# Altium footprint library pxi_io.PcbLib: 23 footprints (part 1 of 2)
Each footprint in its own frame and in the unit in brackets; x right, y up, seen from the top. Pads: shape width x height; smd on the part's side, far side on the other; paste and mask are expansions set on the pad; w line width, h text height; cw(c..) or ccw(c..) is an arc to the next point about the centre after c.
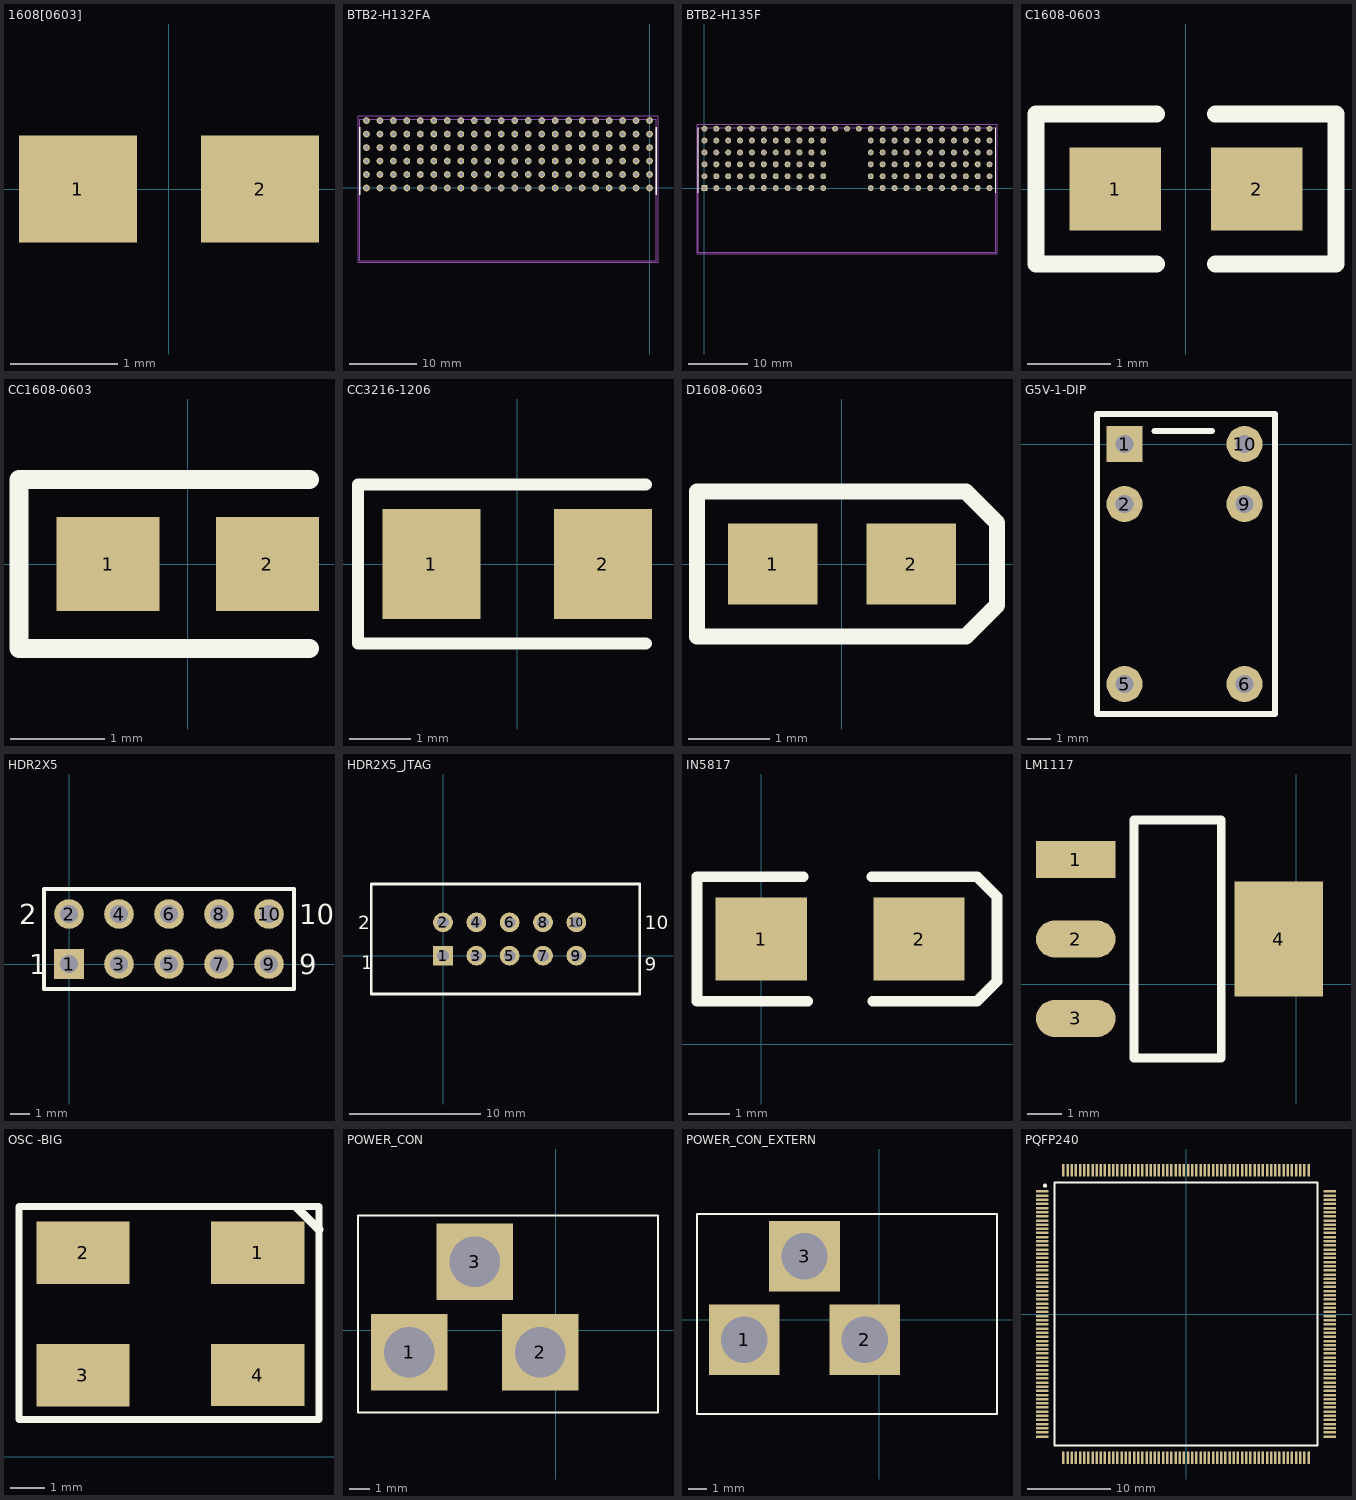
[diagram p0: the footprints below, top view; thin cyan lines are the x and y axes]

## 1608[0603] [mm] "Chip Capacitor; Body 1.6 x 0.8 mm (LxW typ)"
height 1.35
pads (2):
  rect 1.1x1 smd: 1(-0.85,0) 2(0.85,0)

## BTB2-H132FA [mm] "Board-to-Board Connector, Right Angle, Pitch 2mm, 132-Position, Female"
height 7.7
pads (132):
  round 1 hole 0.61: A1(0,0) A2(-2,0) A3(-4,0) A4(-6,0) A5(-8,0) A6(-10,0) A7(-12,0) A8(-14,0) A9(-16,0) A10(-18,0) A11(-20,0) A12(-22,0) A13(-24,0) A14(-26,0) A15(-28,0) A16(-30,0) A17(-32,0) A18(-34,0) A19(-36,0) A20(-38,0) A21(-40,0) A22(-42,0) B1(0,2) B2(-2,2) B3(-4,2) B4(-6,2) B5(-8,2) B6(-10,2) B7(-12,2) B8(-14,2) B9(-16,2) B10(-18,2) B11(-20,2) B12(-22,2) B13(-24,2) B14(-26,2) B15(-28,2) B16(-30,2) B17(-32,2) B18(-34,2) B19(-36,2) B20(-38,2) B21(-40,2) B22(-42,2) C1(0,4) C2(-2,4) C3(-4,4) C4(-6,4) C5(-8,4) C6(-10,4) C7(-12,4) C8(-14,4) C9(-16,4) C10(-18,4) C11(-20,4) C12(-22,4) C13(-24,4) C14(-26,4) C15(-28,4) C16(-30,4) C17(-32,4) C18(-34,4) C19(-36,4) C20(-38,4) C21(-40,4) C22(-42,4) D1(0,6) D2(-2,6) D3(-4,6) D4(-6,6) D5(-8,6) D6(-10,6) D7(-12,6) D8(-14,6) D9(-16,6) D10(-18,6) D11(-20,6) D12(-22,6) D13(-24,6) D14(-26,6) D15(-28,6) D16(-30,6) D17(-32,6) D18(-34,6) D19(-36,6) D20(-38,6) D21(-40,6) D22(-42,6) E1(0,8) E2(-2,8) E3(-4,8) E4(-6,8) E5(-8,8) E6(-10,8) E7(-12,8) E8(-14,8) E9(-16,8) E10(-18,8) E11(-20,8) E12(-22,8) E13(-24,8) E14(-26,8) E15(-28,8) E16(-30,8) E17(-32,8) E18(-34,8) E19(-36,8) E20(-38,8) E21(-40,8) E22(-42,8) F1(0,10) F2(-2,10) F3(-4,10) F4(-6,10) F5(-8,10) F6(-10,10) F7(-12,10) F8(-14,10) F9(-16,10) F10(-18,10) F11(-20,10) F12(-22,10) F13(-24,10) F14(-26,10) F15(-28,10) F16(-30,10) F17(-32,10) F18(-34,10) F19(-36,10) F20(-38,10) F21(-40,10) F22(-42,10)
Top Overlay:
  lines w0.2: -43,-1 -43,9 ; 1,-1 1,9
Mechanical 13:
  lines w0.1: -43,-10.8 -43,10.2 1,10.2 1,-10.8 -43,-10.8
Mechanical 15:
  lines w0.1: -0.5,0 0.5,0 ; 0,-0.5 0,0.5 ; -43.25,-11.05 1.25,-11.05 1.25,10.75 -43.25,10.75 -43.25,-11.05
3D body: height 7.25, standoff 0, extent -43,-2 1,9.4
3D body: height 7.7, standoff -3.7, extent -43,-10.8 0.95,-2.032
3D body: height 7.39, standoff 0.7, extent -42.418,9.8 0.65,10.2
3D body: height 7.8, standoff 7.39, extent -42.418,0.972 0.65,10.2
3D body: height 7.8, standoff 7.39, extent -42.418,-6.38 0.65,0.972
3D body: height 0, standoff -3.3, extent -0.198,-0.199 0.2,0.2
3D body: height 0, standoff -3.3, extent -0.198,1.801 0.2,2.2
3D body: height 0, standoff -3.3, extent -0.198,3.801 0.2,4.2
3D body: height 0, standoff -3.3, extent -0.198,5.801 0.2,6.2
3D body: height 0, standoff -3.3, extent -0.198,7.801 0.2,8.2
3D body: height 0, standoff -3.3, extent -2.198,7.801 -1.8,8.2
3D body: height 0, standoff -3.3, extent -2.198,5.801 -1.8,6.2
3D body: height 0, standoff -3.3, extent -2.198,3.801 -1.8,4.2
3D body: height 0, standoff -3.3, extent -2.198,1.801 -1.8,2.2
3D body: height 0, standoff -3.3, extent -2.198,-0.199 -1.8,0.2
3D body: height 0, standoff -3.3, extent -4.198,7.801 -3.8,8.2
3D body: height 0, standoff -3.3, extent -4.198,5.801 -3.8,6.2
3D body: height 0, standoff -3.3, extent -4.198,3.801 -3.8,4.2
3D body: height 0, standoff -3.3, extent -4.198,1.801 -3.8,2.2
3D body: height 0, standoff -3.3, extent -4.198,-0.199 -3.8,0.2
3D body: height 0, standoff -3.3, extent -6.198,7.801 -5.8,8.2
3D body: height 0, standoff -3.3, extent -6.198,5.801 -5.8,6.2
3D body: height 0, standoff -3.3, extent -6.198,3.801 -5.8,4.2
3D body: height 0, standoff -3.3, extent -6.198,1.801 -5.8,2.2
3D body: height 0, standoff -3.3, extent -6.198,-0.199 -5.8,0.2
3D body: height 0, standoff -3.3, extent -8.198,7.801 -7.8,8.2
3D body: height 0, standoff -3.3, extent -8.198,5.801 -7.8,6.2
3D body: height 0, standoff -3.3, extent -8.198,3.801 -7.8,4.2
3D body: height 0, standoff -3.3, extent -8.198,1.801 -7.8,2.2
3D body: height 0, standoff -3.3, extent -8.198,-0.199 -7.8,0.2
3D body: height 0, standoff -3.3, extent -10.198,7.801 -9.8,8.2
3D body: height 0, standoff -3.3, extent -10.198,5.801 -9.8,6.2
3D body: height 0, standoff -3.3, extent -10.198,3.801 -9.8,4.2
3D body: height 0, standoff -3.3, extent -10.198,1.801 -9.8,2.2
3D body: height 0, standoff -3.3, extent -10.198,-0.199 -9.8,0.2
3D body: height 0, standoff -3.3, extent -12.198,7.801 -11.8,8.2
3D body: height 0, standoff -3.3, extent -12.198,5.801 -11.8,6.2
3D body: height 0, standoff -3.3, extent -12.198,3.801 -11.8,4.2
3D body: height 0, standoff -3.3, extent -12.198,1.801 -11.8,2.2
3D body: height 0, standoff -3.3, extent -12.198,-0.199 -11.8,0.2
3D body: height 0, standoff -3.3, extent -14.198,7.801 -13.8,8.2
3D body: height 0, standoff -3.3, extent -14.198,5.801 -13.8,6.2
3D body: height 0, standoff -3.3, extent -14.198,3.801 -13.8,4.2
3D body: height 0, standoff -3.3, extent -14.198,1.801 -13.8,2.2
3D body: height 0, standoff -3.3, extent -14.198,-0.199 -13.8,0.2
3D body: height 0, standoff -3.3, extent -16.198,7.801 -15.8,8.2
3D body: height 0, standoff -3.3, extent -16.198,5.801 -15.8,6.2
3D body: height 0, standoff -3.3, extent -16.198,3.801 -15.8,4.2
3D body: height 0, standoff -3.3, extent -16.198,1.801 -15.8,2.2
3D body: height 0, standoff -3.3, extent -16.198,-0.199 -15.8,0.2
3D body: height 0, standoff -3.3, extent -18.198,7.801 -17.8,8.2
3D body: height 0, standoff -3.3, extent -18.198,5.801 -17.8,6.2
3D body: height 0, standoff -3.3, extent -18.198,3.801 -17.8,4.2
3D body: height 0, standoff -3.3, extent -18.198,1.801 -17.8,2.2
3D body: height 0, standoff -3.3, extent -18.198,-0.199 -17.8,0.2
3D body: height 0, standoff -3.3, extent -20.198,7.801 -19.8,8.2
3D body: height 0, standoff -3.3, extent -20.198,5.801 -19.8,6.2
3D body: height 0, standoff -3.3, extent -20.198,3.801 -19.8,4.2
3D body: height 0, standoff -3.3, extent -20.198,1.801 -19.8,2.2
3D body: height 0, standoff -3.3, extent -20.198,-0.199 -19.8,0.2
3D body: height 0, standoff -3.3, extent -22.198,7.801 -21.8,8.2
3D body: height 0, standoff -3.3, extent -22.198,5.801 -21.8,6.2
3D body: height 0, standoff -3.3, extent -22.198,3.801 -21.8,4.2
3D body: height 0, standoff -3.3, extent -22.198,1.801 -21.8,2.2
3D body: height 0, standoff -3.3, extent -22.198,-0.199 -21.8,0.2
3D body: height 0, standoff -3.3, extent -24.198,7.801 -23.8,8.2
3D body: height 0, standoff -3.3, extent -24.198,5.801 -23.8,6.2
3D body: height 0, standoff -3.3, extent -24.198,3.801 -23.8,4.2
3D body: height 0, standoff -3.3, extent -24.198,1.801 -23.8,2.2
3D body: height 0, standoff -3.3, extent -24.198,-0.199 -23.8,0.2
3D body: height 0, standoff -3.3, extent -26.198,7.801 -25.8,8.2
3D body: height 0, standoff -3.3, extent -26.198,5.801 -25.8,6.2
3D body: height 0, standoff -3.3, extent -26.198,3.801 -25.8,4.2
3D body: height 0, standoff -3.3, extent -26.198,1.801 -25.8,2.2
3D body: height 0, standoff -3.3, extent -26.198,-0.199 -25.8,0.2
3D body: height 0, standoff -3.3, extent -28.198,7.801 -27.8,8.2
3D body: height 0, standoff -3.3, extent -28.198,5.801 -27.8,6.2
3D body: height 0, standoff -3.3, extent -28.198,3.801 -27.8,4.2
3D body: height 0, standoff -3.3, extent -28.198,1.801 -27.8,2.2
3D body: height 0, standoff -3.3, extent -28.198,-0.199 -27.8,0.2
3D body: height 0, standoff -3.3, extent -30.198,7.801 -29.8,8.2
3D body: height 0, standoff -3.3, extent -30.198,5.801 -29.8,6.2
3D body: height 0, standoff -3.3, extent -30.198,3.801 -29.8,4.2
3D body: height 0, standoff -3.3, extent -30.198,1.801 -29.8,2.2
3D body: height 0, standoff -3.3, extent -30.198,-0.199 -29.8,0.2
3D body: height 0, standoff -3.3, extent -32.198,7.801 -31.8,8.2
3D body: height 0, standoff -3.3, extent -32.198,5.801 -31.8,6.2
3D body: height 0, standoff -3.3, extent -32.198,3.801 -31.8,4.2
3D body: height 0, standoff -3.3, extent -32.198,1.801 -31.8,2.2
3D body: height 0, standoff -3.3, extent -32.198,-0.199 -31.8,0.2
3D body: height 0, standoff -3.3, extent -34.198,7.801 -33.8,8.2
3D body: height 0, standoff -3.3, extent -34.198,5.801 -33.8,6.2
3D body: height 0, standoff -3.3, extent -34.198,3.801 -33.8,4.2
3D body: height 0, standoff -3.3, extent -34.198,1.801 -33.8,2.2
3D body: height 0, standoff -3.3, extent -34.198,-0.199 -33.8,0.2
3D body: height 0, standoff -3.3, extent -36.198,7.801 -35.8,8.2
3D body: height 0, standoff -3.3, extent -36.198,5.801 -35.8,6.2
3D body: height 0, standoff -3.3, extent -36.198,3.801 -35.8,4.2
3D body: height 0, standoff -3.3, extent -36.198,1.801 -35.8,2.2
3D body: height 0, standoff -3.3, extent -36.198,-0.199 -35.8,0.2
3D body: height 0, standoff -3.3, extent -38.198,-0.199 -37.8,0.2
3D body: height 0, standoff -3.3, extent -38.198,1.801 -37.8,2.2
3D body: height 0, standoff -3.3, extent -38.198,3.801 -37.8,4.2
3D body: height 0, standoff -3.3, extent -38.198,5.801 -37.8,6.2
3D body: height 0, standoff -3.3, extent -38.198,7.801 -37.8,8.2
3D body: height 0, standoff -3.3, extent -40.198,-0.199 -39.8,0.2
3D body: height 0, standoff -3.3, extent -40.198,1.801 -39.8,2.2
3D body: height 0, standoff -3.3, extent -40.198,3.801 -39.8,4.2
3D body: height 0, standoff -3.3, extent -40.198,5.801 -39.8,6.2
3D body: height 0, standoff -3.3, extent -40.198,7.801 -39.8,8.2
3D body: height 0, standoff -3.3, extent -42.198,-0.2 -41.8,0.2
3D body: height 0, standoff -3.3, extent -42.198,1.8 -41.8,2.2
3D body: height 0, standoff -3.3, extent -42.198,3.8 -41.8,4.2
3D body: height 0, standoff -3.3, extent -42.198,5.8 -41.8,6.2
3D body: height 0, standoff -3.3, extent -42.198,7.8 -41.8,8.2
3D body: height 0.7, standoff -3.3, extent -40.198,9.8 -39.8,10.2
3D body: height 0.7, standoff -3.3, extent -0.198,9.8 0.2,10.2
3D body: height 0.7, standoff -3.3, extent -4.198,9.8 -3.8,10.2
3D body: height 0.7, standoff -3.3, extent -8.198,9.8 -7.8,10.2
3D body: height 0.7, standoff -3.3, extent -12.198,9.8 -11.8,10.2
3D body: height 0.7, standoff -3.3, extent -16.198,9.8 -15.8,10.2
3D body: height 0.7, standoff -3.3, extent -20.198,9.8 -19.8,10.2
3D body: height 0.7, standoff -3.3, extent -24.198,9.8 -23.8,10.2
3D body: height 0.7, standoff -3.3, extent -28.198,9.8 -27.8,10.2
3D body: height 0.7, standoff -3.3, extent -32.198,9.8 -31.8,10.2
3D body: height 0.7, standoff -3.3, extent -36.198,9.8 -35.8,10.2

## BTB2-H135F [mm] "Board-to-Board Connector, Right Angle, Pitch 2mm, 135-Position, Female"
pads (135):
  rect 1x1 hole 0.61: A1(0,0)
  round 1 hole 0.61: A2(2,0) A3(4,0) A4(6,0) A5(8,0) A6(10,0) A7(12,0) A8(14,0) A9(16,0) A10(18,0) A11(20,0) A15(28,0) A16(30,0) A17(32,0) A18(34,0) A19(36,0) A20(38,0) A21(40,0) A22(42,0) A23(44,0) A24(46,0) A25(48,0) B1(0,2) B2(2,2) B3(4,2) B4(6,2) B5(8,2) B6(10,2) B7(12,2) B8(14,2) B9(16,2) B10(18,2) B11(20,2) B15(28,2) B16(30,2) B17(32,2) B18(34,2) B19(36,2) B20(38,2) B21(40,2) B22(42,2) B23(44,2) B24(46,2) B25(48,2) C1(0,4) C2(2,4) C3(4,4) C4(6,4) C5(8,4) C6(10,4) C7(12,4) C8(14,4) C9(16,4) C10(18,4) C11(20,4) C15(28,4) C16(30,4) C17(32,4) C18(34,4) C19(36,4) C20(38,4) C21(40,4) C22(42,4) C23(44,4) C24(46,4) C25(48,4) D1(0,6) D2(2,6) D3(4,6) D4(6,6) D5(8,6) D6(10,6) D7(12,6) D8(14,6) D9(16,6) D10(18,6) D11(20,6) D15(28,6) D16(30,6) D17(32,6) D18(34,6) D19(36,6) D20(38,6) D21(40,6) D22(42,6) D23(44,6) D24(46,6) D25(48,6) E1(0,8) E2(2,8) E3(4,8) E4(6,8) E5(8,8) E6(10,8) E7(12,8) E8(14,8) E9(16,8) E10(18,8) E11(20,8) E15(28,8) E16(30,8) E17(32,8) E18(34,8) E19(36,8) E20(38,8) E21(40,8) E22(42,8) E23(44,8) E24(46,8) E25(48,8) F1(0,10) F2(2,10) F3(4,10) F4(6,10) F5(8,10) F6(10,10) F7(12,10) F8(14,10) F9(16,10) F10(18,10) F11(20,10) F12(22,10) F13(24,10) F14(26,10) F15(28,10) F16(30,10) F17(32,10) F18(34,10) F19(36,10) F20(38,10) F21(40,10) F22(42,10) F23(44,10) F24(46,10) F25(48,10)
Top Overlay:
  lines w0.2: -1,-0.8 -1,10.2 ; 49,-0.8 49,10.2
Mechanical 13:
  lines w0.1: -1,-10.8 -1,10.2 49,10.2 49,-10.8 -1,-10.8
Mechanical 15:
  lines w0.1: -0.5,0 0.5,0 ; 0,-0.5 0,0.5 ; -1.25,-11.05 -1.25,10.75 49.25,10.75 49.25,-11.05 -1.25,-11.05
3D body: height 7.65, standoff -2.96, extent 21,-2.65 27,-2
3D body: height 7.65, standoff 7.25, extent -0.85,-2 48.85,10.2
3D body: height 7.65, standoff 0.85, extent -0.85,9.8 48.85,10.2
3D body: height 2.86, standoff -0.94, extent 27.702,7.701 28.3,8.299
3D body: height 2.86, standoff -0.94, extent 29.702,7.701 30.3,8.299
3D body: height 2.86, standoff -0.94, extent 31.702,7.701 32.3,8.299
3D body: height 2.86, standoff -0.94, extent 33.702,7.701 34.3,8.299
3D body: height 2.86, standoff -0.94, extent 35.702,7.701 36.3,8.299
3D body: height 2.86, standoff -0.94, extent 37.702,7.701 38.3,8.299
3D body: height 2.86, standoff -0.94, extent 39.702,7.701 40.3,8.299
3D body: height 2.86, standoff -0.94, extent 41.702,7.701 42.3,8.299
3D body: height 2.86, standoff -0.94, extent 43.702,7.701 44.3,8.299
3D body: height 2.86, standoff -0.94, extent 45.702,7.701 46.3,8.299
3D body: height 2.86, standoff -0.94, extent 27.702,5.701 28.3,6.299
3D body: height 2.86, standoff -0.94, extent 29.702,5.701 30.3,6.299
3D body: height 2.86, standoff -0.94, extent 31.702,5.701 32.3,6.299
3D body: height 2.86, standoff -0.94, extent 33.702,5.701 34.3,6.299
3D body: height 2.86, standoff -0.94, extent 35.702,5.701 36.3,6.299
3D body: height 2.86, standoff -0.94, extent 37.702,5.701 38.3,6.299
3D body: height 2.86, standoff -0.94, extent 39.702,5.701 40.3,6.299
3D body: height 2.86, standoff -0.94, extent 41.702,5.701 42.3,6.299
3D body: height 2.86, standoff -0.94, extent 43.702,5.701 44.3,6.299
3D body: height 2.86, standoff -0.94, extent 45.702,5.701 46.3,6.299
3D body: height 2.86, standoff -0.94, extent 47.702,5.701 48.3,6.299
3D body: height 2.86, standoff -0.94, extent 27.702,3.701 28.3,4.299
3D body: height 2.86, standoff -0.94, extent 29.702,3.701 30.3,4.299
3D body: height 2.86, standoff -0.94, extent 31.702,3.701 32.3,4.299
3D body: height 2.86, standoff -0.94, extent 33.702,3.701 34.3,4.299
3D body: height 2.86, standoff -0.94, extent 35.702,3.701 36.3,4.299
3D body: height 2.86, standoff -0.94, extent 37.702,3.701 38.3,4.299
3D body: height 2.86, standoff -0.94, extent 39.702,3.701 40.3,4.299
3D body: height 2.86, standoff -0.94, extent 41.702,3.701 42.3,4.299
3D body: height 2.86, standoff -0.94, extent 43.702,3.701 44.3,4.299
3D body: height 2.86, standoff -0.94, extent 45.702,3.701 46.3,4.299
3D body: height 2.86, standoff -0.94, extent 47.702,3.701 48.3,4.299
3D body: height 2.86, standoff -0.94, extent 27.702,1.701 28.3,2.299
3D body: height 2.86, standoff -0.94, extent 29.702,1.701 30.3,2.299
3D body: height 2.86, standoff -0.94, extent 31.702,1.701 32.3,2.299
3D body: height 2.86, standoff -0.94, extent 33.702,1.701 34.3,2.299
3D body: height 2.86, standoff -0.94, extent 35.702,1.701 36.3,2.299
3D body: height 2.86, standoff -0.94, extent 37.702,1.701 38.3,2.299
3D body: height 2.86, standoff -0.94, extent 39.702,1.701 40.3,2.299
3D body: height 2.86, standoff -0.94, extent 41.702,1.701 42.3,2.299
3D body: height 2.86, standoff -0.94, extent 43.702,1.701 44.3,2.299
3D body: height 2.86, standoff -0.94, extent 45.702,1.701 46.3,2.299
3D body: height 2.86, standoff -0.94, extent 47.702,1.701 48.3,2.299
3D body: height 2.86, standoff -0.94, extent 27.702,-0.299 28.3,0.3
3D body: height 2.86, standoff -0.94, extent 29.702,-0.299 30.3,0.3
3D body: height 2.86, standoff -0.94, extent 31.702,-0.299 32.3,0.3
3D body: height 2.86, standoff -0.94, extent 33.702,-0.299 34.3,0.3
3D body: height 2.86, standoff -0.94, extent 35.702,-0.299 36.3,0.3
3D body: height 2.86, standoff -0.94, extent 37.702,-0.299 38.3,0.3
3D body: height 2.86, standoff -0.94, extent 39.702,-0.299 40.3,0.3
3D body: height 2.86, standoff -0.94, extent 41.702,-0.299 42.3,0.3
3D body: height 2.86, standoff -0.94, extent 43.702,-0.299 44.3,0.3
3D body: height 2.86, standoff -0.94, extent 45.702,-0.299 46.3,0.3
3D body: height 2.86, standoff -0.94, extent 47.702,-0.299 48.3,0.3
3D body: height 2.86, standoff -0.94, extent -0.298,-0.299 0.3,0.299
3D body: height 2.86, standoff -0.94, extent 1.702,-0.299 2.3,0.299
3D body: height 2.86, standoff -0.94, extent 3.702,-0.299 4.3,0.299
3D body: height 2.86, standoff -0.94, extent 5.702,-0.299 6.3,0.299
3D body: height 2.86, standoff -0.94, extent 7.702,-0.299 8.3,0.299
3D body: height 2.86, standoff -0.94, extent 9.702,-0.299 10.3,0.299
3D body: height 2.86, standoff -0.94, extent 11.702,-0.299 12.3,0.299
3D body: height 2.86, standoff -0.94, extent 13.702,-0.299 14.3,0.299
3D body: height 2.86, standoff -0.94, extent 15.702,-0.299 16.3,0.299
3D body: height 2.86, standoff -0.94, extent 17.702,-0.299 18.3,0.299
3D body: height 2.86, standoff -0.94, extent 19.702,-0.299 20.3,0.299
3D body: height 2.86, standoff -0.94, extent -0.298,1.701 0.3,2.299
3D body: height 2.86, standoff -0.94, extent 1.702,1.701 2.3,2.299
3D body: height 2.86, standoff -0.94, extent 3.702,1.701 4.3,2.299
3D body: height 2.86, standoff -0.94, extent 5.702,1.701 6.3,2.299
3D body: height 2.86, standoff -0.94, extent 7.702,1.701 8.3,2.299
3D body: height 2.86, standoff -0.94, extent 9.702,1.701 10.3,2.299
3D body: height 2.86, standoff -0.94, extent 11.702,1.701 12.3,2.299
3D body: height 2.86, standoff -0.94, extent 13.702,1.701 14.3,2.299
3D body: height 2.86, standoff -0.94, extent 15.702,1.701 16.3,2.299
3D body: height 2.86, standoff -0.94, extent 17.702,1.701 18.3,2.299
3D body: height 2.86, standoff -0.94, extent 19.702,1.701 20.3,2.299
3D body: height 2.86, standoff -0.94, extent -0.298,3.701 0.3,4.299
3D body: height 2.86, standoff -0.94, extent 1.702,3.701 2.3,4.299
3D body: height 2.86, standoff -0.94, extent 3.702,3.701 4.3,4.299
3D body: height 2.86, standoff -0.94, extent 5.702,3.701 6.3,4.299
3D body: height 2.86, standoff -0.94, extent 7.702,3.701 8.3,4.299
3D body: height 2.86, standoff -0.94, extent 9.702,3.701 10.3,4.299
3D body: height 2.86, standoff -0.94, extent 11.702,3.701 12.3,4.299
3D body: height 2.86, standoff -0.94, extent 13.702,3.701 14.3,4.299
3D body: height 2.86, standoff -0.94, extent 15.702,3.701 16.3,4.299
3D body: height 2.86, standoff -0.94, extent 17.702,3.701 18.3,4.299
3D body: height 2.86, standoff -0.94, extent 19.702,3.701 20.3,4.299
3D body: height 2.86, standoff -0.94, extent 19.702,5.701 20.3,6.3
3D body: height 2.86, standoff -0.94, extent 17.702,5.701 18.3,6.3
3D body: height 2.86, standoff -0.94, extent 15.702,5.701 16.3,6.3
3D body: height 2.86, standoff -0.94, extent 13.702,5.701 14.3,6.3
3D body: height 2.86, standoff -0.94, extent 11.702,5.701 12.3,6.3
3D body: height 2.86, standoff -0.94, extent 9.702,5.701 10.3,6.3
3D body: height 2.86, standoff -0.94, extent 7.702,5.701 8.3,6.3
3D body: height 2.86, standoff -0.94, extent 5.702,5.701 6.3,6.3
3D body: height 2.86, standoff -0.94, extent 3.702,5.701 4.3,6.3
3D body: height 2.86, standoff -0.94, extent 1.702,5.701 2.3,6.3
3D body: height 2.86, standoff -0.94, extent -0.298,5.701 0.3,6.3
3D body: height 2.86, standoff -0.94, extent 19.702,7.701 20.3,8.3
3D body: height 2.86, standoff -0.94, extent 17.702,7.701 18.3,8.3
3D body: height 2.86, standoff -0.94, extent 15.702,7.701 16.3,8.3
3D body: height 2.86, standoff -0.94, extent 13.702,7.701 14.3,8.3
3D body: height 2.86, standoff -0.94, extent 11.702,7.701 12.3,8.3
3D body: height 2.86, standoff -0.94, extent 9.702,7.701 10.3,8.3
3D body: height 2.86, standoff -0.94, extent 7.702,7.701 8.3,8.3
3D body: height 2.86, standoff -0.94, extent 5.702,7.701 6.3,8.3
3D body: height 2.86, standoff -0.94, extent 3.702,7.701 4.3,8.3
3D body: height 2.86, standoff -0.94, extent 1.702,7.701 2.3,8.3
3D body: height 2.86, standoff -0.94, extent -0.298,7.701 0.3,8.3
3D body: height 2.86, standoff -0.94, extent 47.702,7.701 48.3,8.299
3D body: height 2.91, standoff -1.29, extent 47.732,9.731 48.27,10.27
3D body: height 2.91, standoff -1.29, extent 43.732,9.731 44.27,10.27
3D body: height 2.91, standoff -1.29, extent 39.732,9.731 40.27,10.27
3D body: height 2.91, standoff -1.29, extent 35.732,9.731 36.27,10.27
3D body: height 2.91, standoff -1.29, extent 31.732,9.731 32.27,10.27
3D body: height 2.91, standoff -1.29, extent 27.732,9.731 28.27,10.27
3D body: height 2.91, standoff -1.29, extent 23.732,9.731 24.27,10.27
3D body: height 2.91, standoff -1.29, extent 19.732,9.731 20.27,10.27
3D body: height 2.91, standoff -1.29, extent 15.732,9.731 16.27,10.27
3D body: height 2.91, standoff -1.29, extent 11.732,9.731 12.27,10.27
3D body: height 2.91, standoff -1.29, extent 7.732,9.731 8.27,10.27
3D body: height 2.91, standoff -1.29, extent 3.732,9.731 4.27,10.27
3D body: height 2.91, standoff -1.29, extent -0.268,9.731 0.27,10.27
3D body: height 3.26, standoff -0.94, extent 27,-10.8 48.95,-2
3D body: height 3.26, standoff -0.94, extent -0.95,-10.8 21,-2
3D body: height 0.5, standoff 0, extent -0.95,-2 21,-0.9
3D body: height 0.5, standoff 0, extent 27,-2 48.95,-0.9
3D body: height 7.25, standoff 0.5, extent -0.95,-0.9 21,8.9
3D body: height 7.25, standoff 0.5, extent 27,-0.9 48.95,8.9
3D body: height 2.87, standoff 0, extent -0.95,8.9 21,9.4
3D body: height 2.87, standoff 0, extent 27,8.9 48.95,9.4
3D body: height 7.65, standoff 0.5, extent -0.95,-10.8 21,-0.9
3D body: height 7.65, standoff 0.5, extent 27,-10.8 48.95,-0.9
3D body: height -2.85, standoff -3.75, extent 22.175,-8.725 25.825,-2.65
3D body: height 7.65, standoff 6.75, extent 22.175,-8.725 25.825,-2.65
3D body: height -2.85, standoff -4.18, extent 22.5,-13.8 25.5,-8.725
3D body: height 8.08, standoff 6.75, extent 22.175,-13.8 25.825,-8.725

## C1608-0603 [mm]
pads (2):
  rect 1.1x1 smd: 1(-0.85,0) 2(0.85,0)
Top Overlay:
  lines w0.2: -0.35,-0.9 -1.8,-0.9 -1.8,0.9 -0.35,0.9 ; 0.35,-0.9 1.8,-0.9 1.8,0.9 0.35,0.9

## CC1608-0603 [mm]
pads (2):
  rect 1.1x1 smd: 1(-0.85,0) 2(0.85,0)
Top Overlay:
  lines w0.2: 1.3,-0.9 -1.8,-0.9 -1.8,0.9 1.3,0.9

## CC3216-1206 [mm]
pads (2):
  rect 1.6x1.8 smd: 1(-1.4,0) 2(1.4,0)
Top Overlay:
  lines w0.2: 2.1,-1.3 -2.6,-1.3 -2.6,1.3 2.1,1.3

## D1608-0603 [mm]
pads (2):
  rect 1.1x1 smd: 1(-0.85,0) 2(0.85,0)
Top Overlay:
  lines w0.2: 1.27,-0.889 1.524,-0.889 1.905,-0.508 1.905,0.508 1.524,0.889 1.27,0.889 ; 1.3,-0.889 -1.778,-0.889 -1.778,0.889 1.3,0.889

## G5V-1-DIP [mil]
pads (6):
  rect 60x60 hole 30: 1(200,0)
  round 60 hole 30: 2(200,-100) 5(200,-400) 6(400,-400) 9(400,-100) 10(400,0)
Top Overlay:
  lines w10: 250,22 346,22 ; 154,-450 451,-450 451,50 154,50 154,-450

## HDR2X5 [mm] "Connector; Header; 5x2 Position"
pads (10):
  rect 1.5x1.5 hole 0.9: 1(0,0)
  round 1.5 hole 0.9: 2(0,2.54) 3(2.54,0) 4(2.54,2.54) 5(5.08,0) 6(5.08,2.54) 7(7.62,0) 8(7.62,2.54) 9(10.16,0) 10(10.16,2.54)
Top Overlay:
  lines w0.2: -1.27,-1.27 -1.27,3.81 11.43,3.81 11.43,-1.27 -1.27,-1.27
  text "2" at -2.54,2.032 h1.02
  text "1" at -2.032,-0.508 h1.02
  text "9" at 11.684,-0.508 h1.02
  text "10" at 11.684,2.032 h1.02

## HDR2X5_JTAG [mm] "Connector; Header; 5x2 Position"
pads (10):
  rect 1.5x1.5 hole 0.9: 1(0,0)
  round 1.5 hole 0.9: 2(0,2.54) 3(2.54,0) 4(2.54,2.54) 5(5.08,0) 6(5.08,2.54) 7(7.62,0) 8(7.62,2.54) 9(10.16,0) 10(10.16,2.54)
Top Overlay:
  lines w0.2: -5.461,-2.921 14.986,-2.921 14.986,5.461 -5.461,5.461 -5.461,-2.921
  text "10" at 15.367,2.032 h1.02
  text "9" at 15.367,-1.143 h1.02
  text "1" at -6.223,-1.016 h1.02
  text "2" at -6.477,2.032 h1.02

## IN5817 [mm]
pads (2):
  rect 2.2x2 smd: 1(0,2.54) 2(3.81,2.54)
Top Overlay:
  lines w0.254: 1.016,4.039 -1.549,4.039 -1.549,1.041 1.118,1.041 ; 2.667,4.039 5.207,4.039 5.69,3.556 5.69,1.524 5.207,1.041 2.692,1.041

## LM1117 [mil]
pads (4):
  rect 90x42 smd: 1(-250,141)
  oval 90x42 smd: 2(-250,51) 3(-250,-39)
  rect 100x130 smd: 4(-20,51)
Top Overlay:
  lines w10: -99,186 -184,186 -184,-84 -85,-84 -85,186 -97.5,186

## OSC -BIG [mil]
pads (4):
  rect 105x70 smd: 1(-111,230) 2(-307.85,230) 3(-308,92) 4(-111,92.2)
Top Overlay:
  lines w7.87: -380,42 -380,282 -42,282 -42,42 -380,42
  lines w10: -67,281 -42,256

## POWER_CON [mm]
pads (3):
  rect 3.8x3.8 hole 2.5: 1(-7.264,-1.092) 2(-0.764,-1.092) 3(-4.014,3.408)
Top Overlay:
  lines w0.102: -9.804,-4.064 5.08,-4.064 5.08,5.69 -9.804,5.69 -9.804,-4.064

## POWER_CON_EXTERN [mm]
pads (3):
  rect 3.8x3.8 hole 2.5: 1(-7.264,-1.092) 2(-0.764,-1.092) 3(-4.014,3.408)
Top Overlay:
  lines w0.102: -9.804,-5.08 -9.804,5.69 6.35,5.69 6.35,-5.08 -9.804,-5.08

## PQFP240 [mm] "byTX chaned for cyclone FPGA"
pads (240):
  rect 1.5x0.3 smd: 1(-17.3,14.75) 2(-17.3,14.25) 3(-17.3,13.75) 4(-17.3,13.25) 5(-17.3,12.75) 6(-17.3,12.25) 7(-17.3,11.75) 8(-17.3,11.25) 9(-17.3,10.75) 10(-17.3,10.25) 11(-17.3,9.75) 12(-17.3,9.25) 13(-17.3,8.75) 14(-17.3,8.25) 15(-17.3,7.75) 16(-17.3,7.25) 17(-17.3,6.75) 18(-17.3,6.25) 19(-17.3,5.75) 20(-17.3,5.25) 21(-17.3,4.75) 22(-17.3,4.25) 23(-17.3,3.75) 24(-17.3,3.25) 25(-17.3,2.75) 26(-17.3,2.25) 27(-17.3,1.75) 28(-17.3,1.25) 29(-17.3,0.75) 30(-17.3,0.25) 31(-17.3,-0.25) 32(-17.3,-0.75) 33(-17.3,-1.25) 34(-17.3,-1.75) 35(-17.3,-2.25) 36(-17.3,-2.75) 37(-17.3,-3.25) 38(-17.3,-3.75) 39(-17.3,-4.25) 40(-17.3,-4.75) 41(-17.3,-5.25) 42(-17.3,-5.75) 43(-17.3,-6.25) 44(-17.3,-6.75) 45(-17.3,-7.25) 46(-17.3,-7.75) 47(-17.3,-8.25) 48(-17.3,-8.75) 49(-17.3,-9.25) 50(-17.3,-9.75) 51(-17.3,-10.25) 52(-17.3,-10.75) 53(-17.3,-11.25) 54(-17.3,-11.75) 55(-17.3,-12.25) 56(-17.3,-12.75) 57(-17.3,-13.25) 58(-17.3,-13.75) 59(-17.3,-14.25) 60(-17.3,-14.75) 121(17.3,-14.75) 122(17.3,-14.25) 123(17.3,-13.75) 124(17.3,-13.25) 125(17.3,-12.75) 126(17.3,-12.25) 127(17.3,-11.75) 128(17.3,-11.25) 129(17.3,-10.75) 130(17.3,-10.25) 131(17.3,-9.75) 132(17.3,-9.25) 133(17.3,-8.75) 134(17.3,-8.25) 135(17.3,-7.75) 136(17.3,-7.25) 137(17.3,-6.75) 138(17.3,-6.25) 139(17.3,-5.75) 140(17.3,-5.25) 141(17.3,-4.75) 142(17.3,-4.25) 143(17.3,-3.75) 144(17.3,-3.25) 145(17.3,-2.75) 146(17.3,-2.25) 147(17.3,-1.75) 148(17.3,-1.25) 149(17.3,-0.75) 150(17.3,-0.25) 151(17.3,0.25) 152(17.3,0.75) 153(17.3,1.25) 154(17.3,1.75) 155(17.3,2.25) 156(17.3,2.75) 157(17.3,3.25) 158(17.3,3.75) 159(17.3,4.25) 160(17.3,4.75) 161(17.3,5.25) 162(17.3,5.75) 163(17.3,6.25) 164(17.3,6.75) 165(17.3,7.25) 166(17.3,7.75) 167(17.3,8.25) 168(17.3,8.75) 169(17.3,9.25) 170(17.3,9.75) 171(17.3,10.25) 172(17.3,10.75) 173(17.3,11.25) 174(17.3,11.75) 175(17.3,12.25) 176(17.3,12.75) 177(17.3,13.25) 178(17.3,13.75) 179(17.3,14.25) 180(17.3,14.75)
  rect 0.3x1.5 smd: 61(-14.75,-17.3) 62(-14.25,-17.3) 63(-13.75,-17.3) 64(-13.25,-17.3) 65(-12.75,-17.3) 66(-12.25,-17.3) 67(-11.75,-17.3) 68(-11.25,-17.3) 69(-10.75,-17.3) 70(-10.25,-17.3) 71(-9.75,-17.3) 72(-9.25,-17.3) 73(-8.75,-17.3) 74(-8.25,-17.3) 75(-7.75,-17.3) 76(-7.25,-17.3) 77(-6.75,-17.3) 78(-6.25,-17.3) 79(-5.75,-17.3) 80(-5.25,-17.3) 81(-4.75,-17.3) 82(-4.25,-17.3) 83(-3.75,-17.3) 84(-3.25,-17.3) 85(-2.75,-17.3) 86(-2.25,-17.3) 87(-1.75,-17.3) 88(-1.25,-17.3) 89(-0.75,-17.3) 90(-0.25,-17.3) 91(0.25,-17.3) 92(0.75,-17.3) 93(1.25,-17.3) 94(1.75,-17.3) 95(2.25,-17.3) 96(2.75,-17.3) 97(3.25,-17.3) 98(3.75,-17.3) 99(4.25,-17.3) 100(4.75,-17.3) 101(5.25,-17.3) 102(5.75,-17.3) 103(6.25,-17.3) 104(6.75,-17.3) 105(7.25,-17.3) 106(7.75,-17.3) 107(8.25,-17.3) 108(8.75,-17.3) 109(9.25,-17.3) 110(9.75,-17.3) 111(10.25,-17.3) 112(10.75,-17.3) 113(11.25,-17.3) 114(11.75,-17.3) 115(12.25,-17.3) 116(12.75,-17.3) 117(13.25,-17.3) 118(13.75,-17.3) 119(14.25,-17.3) 120(14.75,-17.3) 181(14.75,17.3) 182(14.25,17.3) 183(13.75,17.3) 184(13.25,17.3) 185(12.75,17.3) 186(12.25,17.3) 187(11.75,17.3) 188(11.25,17.3) 189(10.75,17.3) 190(10.25,17.3) 191(9.75,17.3) 192(9.25,17.3) 193(8.75,17.3) 194(8.25,17.3) 195(7.75,17.3) 196(7.25,17.3) 197(6.75,17.3) 198(6.25,17.3) 199(5.75,17.3) 200(5.25,17.3) 201(4.75,17.3) 202(4.25,17.3) 203(3.75,17.3) 204(3.25,17.3) 205(2.75,17.3) 206(2.25,17.3) 207(1.75,17.3) 208(1.25,17.3) 209(0.75,17.3) 210(0.25,17.3) 211(-0.25,17.3) 212(-0.75,17.3) 213(-1.25,17.3) 214(-1.75,17.3) 215(-2.25,17.3) 216(-2.75,17.3) 217(-3.25,17.3) 218(-3.75,17.3) 219(-4.25,17.3) 220(-4.75,17.3) 221(-5.25,17.3) 222(-5.75,17.3) 223(-6.25,17.3) 224(-6.75,17.3) 225(-7.25,17.3) 226(-7.75,17.3) 227(-8.25,17.3) 228(-8.75,17.3) 229(-9.25,17.3) 230(-9.75,17.3) 231(-10.25,17.3) 232(-10.75,17.3) 233(-11.25,17.3) 234(-11.75,17.3) 235(-12.25,17.3) 236(-12.75,17.3) 237(-13.25,17.3) 238(-13.75,17.3) 239(-14.25,17.3) 240(-14.75,17.3)
Top Overlay:
  circle w0.25: c-16.975,15.45 r0.125
  lines w0.2: -15.825,-15.825 15.825,-15.825 15.825,15.825 -15.825,15.825 -15.825,-15.825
